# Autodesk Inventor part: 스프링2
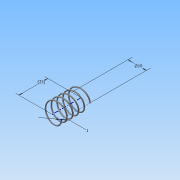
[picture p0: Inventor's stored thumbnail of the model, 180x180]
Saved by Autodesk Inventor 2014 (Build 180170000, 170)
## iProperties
Created: 2015-06
Part Number: 스프링2
Material: 강철, 연강
Document SubType Name: Modeling
Designer: Administrator
Density: 7.86 g/cm^3
Appearance: 강철
Mass: 1.52988 g
Surface Area: 7.87024 cm^2
Volume: 0.194641 cm^3
Author: Administrator
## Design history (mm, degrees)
sketch "스케치1"
  geometry: L1 (0, 0)-(8, 0); L2 (8, 0)-(8, 14.5); L3 (8, 14.5)-(0, 14.5); L4 (0, 14.5)-(0, 0); C1 r 0.5 at (8, 0)
  constraints: 8 end point, 2 parallel, 1 centre point, 1 coincident, 1 horizontal, 1 perpendicular
  dimensions: "d0" = 14.5 distance of L3.end L1.start (derived); "d1" = 16 diameter of L2 L4; "d2" = 1 diameter of C1
feature "코일1" sketch "스케치1" pitch "d3" = 10; turns "d5" = 5; dims "d4" = 14.5 (= d0), "d6" = 0, angle "d7" = 90 deg, angle "d8" = 90 deg, "d9" = 0, "d10" = 0
sketch "스케치2"
  geometry: L1 (-8.5, 0)-(-7.5, 0) reference; 1 further point
  constraints: 1 horizontal alignment
extrude "돌출1" cut sketch "스케치2" stored distance "d11" = 10; taper "d12" = 0 deg
node "작업 평면1"
sketch "스케치3"
  geometry: L1 (-7.5, 0)-(-8.5, 0) reference; 1 further point
  constraints: 1 horizontal alignment
extrude "돌출2" cut sketch "스케치3" stored distance "d14" = 10; taper "d15" = 0 deg
node "솔리드1"
node "절단 모서리 투영1"
node "절단 모서리 투영2"
other parameters: "d13" = 14.5 (= d0)
